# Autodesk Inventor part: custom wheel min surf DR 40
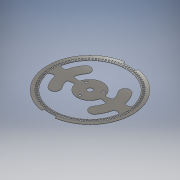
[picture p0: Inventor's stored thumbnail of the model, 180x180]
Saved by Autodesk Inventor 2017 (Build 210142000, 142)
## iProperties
Created: 2016-09
Part Number: custom wheel min surf DR 40
Material: Generic
Document SubType Name: Modeling
Designer: Radek
Density: 1 g/cm^3
Appearance: Mirror
Author: Radek
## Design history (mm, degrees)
workplane "Work Plane1"
sketch "Sketch1"
  geometry: L1 (-46.781, 4.422)-(-44.253, 4.183) reference; L2 (-44.362, 2.791)-(-46.897, 2.951) reference; L3 (-46.411, 7.351)-(-43.903, 6.954) reference; L4 (-44.099, 5.571)-(-46.619, 5.889) reference; L5 (-45.858, 10.251)-(-43.38, 9.696) reference; L6 (-43.663, 8.329)-(-46.158, 8.805) reference; L7 (-45.124, 13.11)-(-42.685, 12.401) reference; L8 (-43.054, 11.054)-(-45.514, 11.686) reference; L9 (-44.212, 15.917)-(-41.822, 15.057) reference; L10 (-42.274, 13.736)-(-44.69, 14.521) reference; L11 (-43.125, 18.662)-(-40.794, 17.653) reference; L12 (-41.329, 16.363)-(-43.69, 17.298) reference; L13 (-41.868, 21.333)-(-39.605, 20.18) reference; L14 (-40.22, 18.926)-(-42.518, 20.007) reference; L15 (-40.446, 23.92)-(-38.26, 22.627) reference; L16 (-38.952, 21.414)-(-41.178, 22.638) reference; L17 (-38.865, 26.412)-(-36.764, 24.985) reference; L18 (-37.53, 23.818)-(-39.675, 25.179) reference; L19 (-37.129, 28.801)-(-35.122, 27.244) reference; L20 (-35.961, 26.127)-(-38.016, 27.62) reference; L21 (-35.248, 31.075)-(-33.342, 29.395) reference; L22 (-34.249, 28.333)-(-36.206, 29.953) reference; L23 (-33.227, 33.227)-(-31.431, 31.431) reference; L24 (-32.403, 30.428)-(-34.254, 32.167) reference; L25 (-31.075, 35.248)-(-29.395, 33.342) reference; L26 (-30.428, 32.403)-(-32.167, 34.254) reference; L27 (-28.801, 37.129)-(-27.244, 35.122) reference; L28 (-28.333, 34.249)-(-29.953, 36.206) reference; L29 (-26.412, 38.865)-(-24.985, 36.764) reference; L30 (-26.127, 35.961)-(-27.62, 38.016) reference; L31 (-23.92, 40.446)-(-22.627, 38.26) reference; L32 (-23.818, 37.53)-(-25.179, 39.675) reference; L33 (-21.333, 41.868)-(-20.18, 39.605) reference; L34 (-21.414, 38.952)-(-22.638, 41.178) reference; L35 (-18.662, 43.125)-(-17.653, 40.794) reference; L36 (-18.926, 40.22)-(-20.007, 42.518) reference; L37 (-15.917, 44.212)-(-15.057, 41.822) reference; L38 (-16.363, 41.329)-(-17.298, 43.69) reference; L39 (-13.11, 45.124)-(-12.401, 42.685) reference; L40 (-13.736, 42.274)-(-14.521, 44.69) reference; L41 (-10.251, 45.858)-(-9.696, 43.38) reference; L42 (-11.054, 43.054)-(-11.686, 45.514) reference; L43 (-7.351, 46.411)-(-6.954, 43.903) reference; L44 (-8.329, 43.663)-(-8.805, 46.158) reference; L45 (-4.422, 46.781)-(-4.183, 44.253) reference; L46 (-5.571, 44.099)-(-5.889, 46.619) reference; L47 (-1.476, 46.967)-(-1.396, 44.428) reference; L48 (-2.791, 44.362)-(-2.951, 46.897) reference; L49 (1.476, 46.967)-(1.396, 44.428) reference; L50 (0, 44.45)-(0, 46.99) reference; L51 (4.422, 46.781)-(4.183, 44.253) reference; L52 (2.791, 44.362)-(2.951, 46.897) reference; L53 (7.351, 46.411)-(6.954, 43.903) reference; L54 (5.571, 44.099)-(5.889, 46.619) reference; L55 (10.251, 45.858)-(9.696, 43.38) reference; L56 (8.329, 43.663)-(8.805, 46.158) reference; L57 (13.11, 45.124)-(12.401, 42.685) reference; L58 (11.054, 43.054)-(11.686, 45.514) reference; L59 (15.917, 44.212)-(15.057, 41.822) reference; L60 (13.736, 42.274)-(14.521, 44.69) reference; L61 (18.662, 43.125)-(17.653, 40.794) reference; L62 (16.363, 41.329)-(17.298, 43.69) reference; L63 (21.333, 41.868)-(20.18, 39.605) reference; L64 (18.926, 40.22)-(20.007, 42.518) reference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; C1 r 50.8 at (0, 0) reference; C2 r 2.984 at (0, 0) reference; C3 r 1.524 at (0, 6.553) reference; C4 r 1.524 at (10.339, 5.969) reference; C5 r 2.984 at (0, 0) reference; C6 r 1.524 at (0, -11.938) reference; C7 r 1.524 at (-5.675, -3.277) reference; C8 r 1.524 at (-10.339, 5.969) reference; C9 r 1.524 at (5.675, -3.277) reference; C10 r 50.8 at (0, 0) reference; C11 r 1.524 at (-5.675, -3.277) reference; C12 r 1.524 at (-10.339, 5.969) reference; C13 r 1.524 at (0, 6.553) reference; C14 r 1.524 at (10.339, 5.969) reference; C15 r 1.524 at (5.675, -3.277) reference; C16 r 1.524 at (0, -11.938) reference; C17 r 2.984 at (0, 0) reference; A1 r 17.081 centre (0, 0) between (0, -17.081) and (17.081, 0) reference; A2 r 17.081 centre (0, 0) between (0, 17.081) and (-17.081, 0) reference; A3 r 43.18 centre (0, 0) between (0, 43.18) and (-43.18, 0) reference; A4 r 43.18 centre (0, 0) between (0, -43.18) and (43.18, 0) reference; A5 r 44.45 centre (0, 0) between (-44.253, 4.183) and (-44.362, 2.791) reference; A6 r 46.99 centre (0, 0) between (-46.781, 4.422) and (-46.897, 2.951) reference; A7 r 44.45 centre (0, 0) between (-43.903, 6.954) and (-44.099, 5.571) reference; A8 r 46.99 centre (0, 0) between (-46.411, 7.351) and (-46.619, 5.889) reference; A9 r 44.45 centre (0, 0) between (-43.38, 9.696) and (-43.663, 8.329) reference; A10 r 46.99 centre (0, 0) between (-45.858, 10.251) and (-46.158, 8.805) reference; A11 r 44.45 centre (0, 0) between (-42.685, 12.401) and (-43.054, 11.054) reference; A12 r 46.99 centre (0, 0) between (-45.124, 13.11) and (-45.514, 11.686) reference; A13 r 44.45 centre (0, 0) between (-41.822, 15.057) and (-42.274, 13.736) reference; A14 r 46.99 centre (0, 0) between (-44.212, 15.917) and (-44.69, 14.521) reference; A15 r 44.45 centre (0, 0) between (-40.794, 17.653) and (-41.329, 16.363) reference; A16 r 46.99 centre (0, 0) between (-43.125, 18.662) and (-43.69, 17.298) reference; A17 r 44.45 centre (0, 0) between (-39.605, 20.18) and (-40.22, 18.926) reference; A18 r 46.99 centre (0, 0) between (-41.868, 21.333) and (-42.518, 20.007) reference; A19 r 44.45 centre (0, 0) between (-38.26, 22.627) and (-38.952, 21.414) reference; A20 r 46.99 centre (0, 0) between (-40.446, 23.92) and (-41.178, 22.638) reference; A21 r 44.45 centre (0, 0) between (-36.764, 24.985) and (-37.53, 23.818) reference; A22 r 46.99 centre (0, 0) between (-38.865, 26.412) and (-39.675, 25.179) reference; A23 r 44.45 centre (0, 0) between (-35.122, 27.244) and (-35.961, 26.127) reference; A24 r 46.99 centre (0, 0) between (-37.129, 28.801) and (-38.016, 27.62) reference; A25 r 44.45 centre (0, 0) between (-33.342, 29.395) and (-34.249, 28.333) reference; A26 r 46.99 centre (0, 0) between (-35.248, 31.075) and (-36.206, 29.953) reference; A27 r 44.45 centre (0, 0) between (-31.431, 31.431) and (-32.403, 30.428) reference; A28 r 46.99 centre (0, 0) between (-33.227, 33.227) and (-34.254, 32.167) reference; A29 r 44.45 centre (0, 0) between (-29.395, 33.342) and (-30.428, 32.403) reference; A30 r 46.99 centre (0, 0) between (-31.075, 35.248) and (-32.167, 34.254) reference; A31 r 44.45 centre (0, 0) between (-27.244, 35.122) and (-28.333, 34.249) reference; A32 r 46.99 centre (0, 0) between (-28.801, 37.129) and (-29.953, 36.206) reference; A33 r 44.45 centre (0, 0) between (-24.985, 36.764) and (-26.127, 35.961) reference; A34 r 46.99 centre (0, 0) between (-26.412, 38.865) and (-27.62, 38.016) reference; A35 r 44.45 centre (0, 0) between (-22.627, 38.26) and (-23.818, 37.53) reference; A36 r 46.99 centre (0, 0) between (-23.92, 40.446) and (-25.179, 39.675) reference; A37 r 44.45 centre (0, 0) between (-20.18, 39.605) and (-21.414, 38.952) reference; A38 r 46.99 centre (0, 0) between (-21.333, 41.868) and (-22.638, 41.178) reference; A39 r 44.45 centre (0, 0) between (-17.653, 40.794) and (-18.926, 40.22) reference; A40 r 46.99 centre (0, 0) between (-18.662, 43.125) and (-20.007, 42.518) reference; A41 r 44.45 centre (0, 0) between (-15.057, 41.822) and (-16.363, 41.329) reference; A42 r 46.99 centre (0, 0) between (-15.917, 44.212) and (-17.298, 43.69) reference; A43 r 44.45 centre (0, 0) between (-12.401, 42.685) and (-13.736, 42.274) reference; A44 r 46.99 centre (0, 0) between (-13.11, 45.124) and (-14.521, 44.69) reference; A45 r 44.45 centre (0, 0) between (-9.696, 43.38) and (-11.054, 43.054) reference; A46 r 46.99 centre (0, 0) between (-10.251, 45.858) and (-11.686, 45.514) reference; A47 r 44.45 centre (0, 0) between (-6.954, 43.903) and (-8.329, 43.663) reference; A48 r 46.99 centre (0, 0) between (-7.351, 46.411) and (-8.805, 46.158) reference; A49 r 44.45 centre (0, 0) between (-4.183, 44.253) and (-5.571, 44.099) reference; A50 r 46.99 centre (0, 0) between (-4.422, 46.781) and (-5.889, 46.619) reference; A51 r 44.45 centre (0, 0) between (-1.396, 44.428) and (-2.791, 44.362) reference; A52 r 46.99 centre (0, 0) between (-1.476, 46.967) and (-2.951, 46.897) reference; A53 r 44.45 centre (0, 0) between (1.396, 44.428) and (0, 44.45) reference; A54 r 46.99 centre (0, 0) between (1.476, 46.967) and (0, 46.99) reference; A55 r 44.45 centre (0, 0) between (4.183, 44.253) and (2.791, 44.362) reference; A56 r 46.99 centre (0, 0) between (4.422, 46.781) and (2.951, 46.897) reference; A57 r 44.45 centre (0, 0) between (6.954, 43.903) and (5.571, 44.099) reference; A58 r 46.99 centre (0, 0) between (7.351, 46.411) and (5.889, 46.619) reference; A59 r 44.45 centre (0, 0) between (9.696, 43.38) and (8.329, 43.663) reference; A60 r 46.99 centre (0, 0) between (10.251, 45.858) and (8.805, 46.158) reference; A61 r 44.45 centre (0, 0) between (12.401, 42.685) and (11.054, 43.054) reference; A62 r 46.99 centre (0, 0) between (13.11, 45.124) and (11.686, 45.514) reference; A63 r 44.45 centre (0, 0) between (15.057, 41.822) and (13.736, 42.274) reference; A64 r 46.99 centre (0, 0) between (15.917, 44.212) and (14.521, 44.69) reference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; 1 further point
  constraints: 8 end point, 2 collinear, 1 parallel
extrude "Extrusion2" new body sketch "Sketch1" distance "d2" = 0.3; taper "d3" = 0 deg
sketch "Sketch2"
  geometry: L1 (-46.781, 4.422)-(-44.253, 4.183) reference; L2 (-44.362, 2.791)-(-46.897, 2.951) reference; L3 (-46.411, 7.351)-(-43.903, 6.954) reference; L4 (-44.099, 5.571)-(-46.619, 5.889) reference; L5 (-45.858, 10.251)-(-43.38, 9.696) reference; L6 (-43.663, 8.329)-(-46.158, 8.805) reference; L7 (-45.124, 13.11)-(-42.685, 12.401) reference; L8 (-43.054, 11.054)-(-45.514, 11.686) reference; L9 (-44.212, 15.917)-(-41.822, 15.057) reference; L10 (-42.274, 13.736)-(-44.69, 14.521) reference; L11 (-43.125, 18.662)-(-40.794, 17.653) reference; L12 (-41.329, 16.363)-(-43.69, 17.298) reference; L13 (-41.868, 21.333)-(-39.605, 20.18) reference; L14 (-40.22, 18.926)-(-42.518, 20.007) reference; L15 (-40.446, 23.92)-(-38.26, 22.627) reference; L16 (-38.952, 21.414)-(-41.178, 22.638) reference; L17 (-38.865, 26.412)-(-36.764, 24.985) reference; L18 (-37.53, 23.818)-(-39.675, 25.179) reference; L19 (-37.129, 28.801)-(-35.122, 27.244) reference; L20 (-35.961, 26.127)-(-38.016, 27.62) reference; L21 (-35.248, 31.075)-(-33.342, 29.395) reference; L22 (-34.249, 28.333)-(-36.206, 29.953) reference; L23 (-33.227, 33.227)-(-31.431, 31.431) reference; L24 (-32.403, 30.428)-(-34.254, 32.167) reference; L25 (-31.075, 35.248)-(-29.395, 33.342) reference; L26 (-30.428, 32.403)-(-32.167, 34.254) reference; L27 (-28.801, 37.129)-(-27.244, 35.122) reference; L28 (-28.333, 34.249)-(-29.953, 36.206) reference; L29 (-26.412, 38.865)-(-24.985, 36.764) reference; L30 (-26.127, 35.961)-(-27.62, 38.016) reference; L31 (-23.92, 40.446)-(-22.627, 38.26) reference; L32 (-23.818, 37.53)-(-25.179, 39.675) reference; L33 (-21.333, 41.868)-(-20.18, 39.605) reference; L34 (-21.414, 38.952)-(-22.638, 41.178) reference; L35 (-18.662, 43.125)-(-17.653, 40.794) reference; L36 (-18.926, 40.22)-(-20.007, 42.518) reference; L37 (-15.917, 44.212)-(-15.057, 41.822) reference; L38 (-16.363, 41.329)-(-17.298, 43.69) reference; L39 (-13.11, 45.124)-(-12.401, 42.685) reference; L40 (-13.736, 42.274)-(-14.521, 44.69) reference; L41 (-10.251, 45.858)-(-9.696, 43.38) reference; L42 (-11.054, 43.054)-(-11.686, 45.514) reference; L43 (-7.351, 46.411)-(-6.954, 43.903) reference; L44 (-8.329, 43.663)-(-8.805, 46.158) reference; L45 (-4.422, 46.781)-(-4.183, 44.253) reference; L46 (-5.571, 44.099)-(-5.889, 46.619) reference; L47 (-1.476, 46.967)-(-1.396, 44.428) reference; L48 (-2.791, 44.362)-(-2.951, 46.897) reference; L49 (1.476, 46.967)-(1.396, 44.428) reference; L50 (0, 44.45)-(0, 46.99) reference; L51 (4.422, 46.781)-(4.183, 44.253) reference; L52 (2.791, 44.362)-(2.951, 46.897) reference; L53 (7.351, 46.411)-(6.954, 43.903) reference; L54 (5.571, 44.099)-(5.889, 46.619) reference; L55 (10.251, 45.858)-(9.696, 43.38) reference; L56 (8.329, 43.663)-(8.805, 46.158) reference; L57 (13.11, 45.124)-(12.401, 42.685) reference; L58 (11.054, 43.054)-(11.686, 45.514) reference; L59 (15.917, 44.212)-(15.057, 41.822) reference; L60 (13.736, 42.274)-(14.521, 44.69) reference; L61 (18.662, 43.125)-(17.653, 40.794) reference; L62 (16.363, 41.329)-(17.298, 43.69) reference; L63 (21.333, 41.868)-(20.18, 39.605) reference; L64 (18.926, 40.22)-(20.007, 42.518) reference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; C1 r 50.8 at (0, 0) reference; C2 r 1.524 at (-5.675, -3.277) reference; C3 r 1.524 at (-10.339, 5.969) reference; C4 r 1.524 at (0, 6.553) reference; C5 r 1.524 at (10.339, 5.969) reference; C6 r 1.524 at (5.675, -3.277) reference; C7 r 1.524 at (0, -11.938) reference; C8 r 2.984 at (0, 0) reference; A1 r 44.45 centre (0, 0) between (-44.253, 4.183) and (-44.362, 2.791) reference; A2 r 46.99 centre (0, 0) between (-46.781, 4.422) and (-46.897, 2.951) reference; A3 r 44.45 centre (0, 0) between (-43.903, 6.954) and (-44.099, 5.571) reference; A4 r 46.99 centre (0, 0) between (-46.411, 7.351) and (-46.619, 5.889) reference; A5 r 44.45 centre (0, 0) between (-43.38, 9.696) and (-43.663, 8.329) reference; A6 r 46.99 centre (0, 0) between (-45.858, 10.251) and (-46.158, 8.805) reference; A7 r 44.45 centre (0, 0) between (-42.685, 12.401) and (-43.054, 11.054) reference; A8 r 46.99 centre (0, 0) between (-45.124, 13.11) and (-45.514, 11.686) reference; A9 r 44.45 centre (0, 0) between (-41.822, 15.057) and (-42.274, 13.736) reference; A10 r 46.99 centre (0, 0) between (-44.212, 15.917) and (-44.69, 14.521) reference; A11 r 44.45 centre (0, 0) between (-40.794, 17.653) and (-41.329, 16.363) reference; A12 r 46.99 centre (0, 0) between (-43.125, 18.662) and (-43.69, 17.298) reference; A13 r 44.45 centre (0, 0) between (-39.605, 20.18) and (-40.22, 18.926) reference; A14 r 46.99 centre (0, 0) between (-41.868, 21.333) and (-42.518, 20.007) reference; A15 r 44.45 centre (0, 0) between (-38.26, 22.627) and (-38.952, 21.414) reference; A16 r 46.99 centre (0, 0) between (-40.446, 23.92) and (-41.178, 22.638) reference; A17 r 44.45 centre (0, 0) between (-36.764, 24.985) and (-37.53, 23.818) reference; A18 r 46.99 centre (0, 0) between (-38.865, 26.412) and (-39.675, 25.179) reference; A19 r 44.45 centre (0, 0) between (-35.122, 27.244) and (-35.961, 26.127) reference; A20 r 46.99 centre (0, 0) between (-37.129, 28.801) and (-38.016, 27.62) reference; A21 r 44.45 centre (0, 0) between (-33.342, 29.395) and (-34.249, 28.333) reference; A22 r 46.99 centre (0, 0) between (-35.248, 31.075) and (-36.206, 29.953) reference; A23 r 44.45 centre (0, 0) between (-31.431, 31.431) and (-32.403, 30.428) reference; A24 r 46.99 centre (0, 0) between (-33.227, 33.227) and (-34.254, 32.167) reference; A25 r 44.45 centre (0, 0) between (-29.395, 33.342) and (-30.428, 32.403) reference; A26 r 46.99 centre (0, 0) between (-31.075, 35.248) and (-32.167, 34.254) reference; A27 r 44.45 centre (0, 0) between (-27.244, 35.122) and (-28.333, 34.249) reference; A28 r 46.99 centre (0, 0) between (-28.801, 37.129) and (-29.953, 36.206) reference; A29 r 44.45 centre (0, 0) between (-24.985, 36.764) and (-26.127, 35.961) reference; A30 r 46.99 centre (0, 0) between (-26.412, 38.865) and (-27.62, 38.016) reference; A31 r 44.45 centre (0, 0) between (-22.627, 38.26) and (-23.818, 37.53) reference; A32 r 46.99 centre (0, 0) between (-23.92, 40.446) and (-25.179, 39.675) reference; A33 r 44.45 centre (0, 0) between (-20.18, 39.605) and (-21.414, 38.952) reference; A34 r 46.99 centre (0, 0) between (-21.333, 41.868) and (-22.638, 41.178) reference; A35 r 44.45 centre (0, 0) between (-17.653, 40.794) and (-18.926, 40.22) reference; A36 r 46.99 centre (0, 0) between (-18.662, 43.125) and (-20.007, 42.518) reference; A37 r 44.45 centre (0, 0) between (-15.057, 41.822) and (-16.363, 41.329) reference; A38 r 46.99 centre (0, 0) between (-15.917, 44.212) and (-17.298, 43.69) reference; A39 r 44.45 centre (0, 0) between (-12.401, 42.685) and (-13.736, 42.274) reference; A40 r 46.99 centre (0, 0) between (-13.11, 45.124) and (-14.521, 44.69) reference; A41 r 44.45 centre (0, 0) between (-9.696, 43.38) and (-11.054, 43.054) reference; A42 r 46.99 centre (0, 0) between (-10.251, 45.858) and (-11.686, 45.514) reference; A43 r 44.45 centre (0, 0) between (-6.954, 43.903) and (-8.329, 43.663) reference; A44 r 46.99 centre (0, 0) between (-7.351, 46.411) and (-8.805, 46.158) reference; A45 r 44.45 centre (0, 0) between (-4.183, 44.253) and (-5.571, 44.099) reference; A46 r 46.99 centre (0, 0) between (-4.422, 46.781) and (-5.889, 46.619) reference; A47 r 44.45 centre (0, 0) between (-1.396, 44.428) and (-2.791, 44.362) reference; A48 r 46.99 centre (0, 0) between (-1.476, 46.967) and (-2.951, 46.897) reference; A49 r 44.45 centre (0, 0) between (1.396, 44.428) and (0, 44.45) reference; A50 r 46.99 centre (0, 0) between (1.476, 46.967) and (0, 46.99) reference; A51 r 44.45 centre (0, 0) between (4.183, 44.253) and (2.791, 44.362) reference; A52 r 46.99 centre (0, 0) between (4.422, 46.781) and (2.951, 46.897) reference; A53 r 44.45 centre (0, 0) between (6.954, 43.903) and (5.571, 44.099) reference; A54 r 46.99 centre (0, 0) between (7.351, 46.411) and (5.889, 46.619) reference; A55 r 44.45 centre (0, 0) between (9.696, 43.38) and (8.329, 43.663) reference; A56 r 46.99 centre (0, 0) between (10.251, 45.858) and (8.805, 46.158) reference; A57 r 44.45 centre (0, 0) between (12.401, 42.685) and (11.054, 43.054) reference; A58 r 46.99 centre (0, 0) between (13.11, 45.124) and (11.686, 45.514) reference; A59 r 44.45 centre (0, 0) between (15.057, 41.822) and (13.736, 42.274) reference; A60 r 46.99 centre (0, 0) between (15.917, 44.212) and (14.521, 44.69) reference; A61 r 44.45 centre (0, 0) between (17.653, 40.794) and (16.363, 41.329) reference; A62 r 46.99 centre (0, 0) between (18.662, 43.125) and (17.298, 43.69) reference; A63 r 44.45 centre (0, 0) between (20.18, 39.605) and (18.926, 40.22) reference; A64 r 46.99 centre (0, 0) between (21.333, 41.868) and (20.007, 42.518) reference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; 1 further point
  constraints: 8 end point, 1 collinear
extrude "Extrusion3" cut sketch "Sketch2" stored distance "d4" = 0.254; taper "d5" = 0 deg
sketch "Sketch3" dims "d20" = 9.26667 (= 0.5 x holediameter), "d21" = 13.10505 (= 1.41421 x d20)
  geometry: L1 (-10.339, 5.969)-(10.339, 5.969); L2 (0, 0)-(50.8, 0); L3 (0, 44.45)-(0, 46.99) reference; L4 (0, 0)-(0, 50.8); L5 (0, 30)-(0, 16.895); L6 (0, 50.165)-(0, 48.26) reference; L7 (-48.26, 0)-(-50.165, 0) reference; L8 (0, 0)-(29.843, 16.148); L9 (0, 50.8)-(0, 50.165); L10 (11.443, 12.43)-(29.194, 31.713); L11 (-11.443, 12.43)-(-29.194, 31.713); C1 r 2.984 at (0, 0) reference; C2 r 15.25 at (0, 0); C3 r 1.524 at (-10.339, 5.969) reference; C4 r 1.524 at (0, -11.938) reference; C5 r 1.524 at (10.339, 5.969) reference; C6 r 1.524 at (-5.675, -3.277) reference; C7 r 1.524 at (5.675, -3.277) reference; A1 r 50.8 centre (0, 0) between (50.8, 0) and (0, 50.8) reference; A2 r 48.26 centre (0, 0) between (0, 48.26) and (-48.26, 0) reference; A3 r 50.165 centre (0, 0) between (0, 50.165) and (-50.165, 0) reference; A4 r 50.165 centre (0, 0) between (-20.154, -45.939) and (22.037, -45.066); A5 r 48.26 centre (0, 0) between (-19.033, -44.348) and (20.956, -43.472); 3 further points; 3 other entities
  constraints: 16 end point, 8 point on circle, 3 centre point, 3 coincident, 2 midpoint, 2 vertical, 1 collinear, 1 horizontal, 1 parallel, 1 point on line, 1 vertical alignment, 19 other
  dimensions: "d9" = 30.5 diameter of C2; "d18" = 0 distance between parallel lines of L4 L5; "d19" = 30 distance of point (0, 0) L5.start (= offaxis); "d24" = 7.44061 dimension on point (0, 0) L5.start point (-20.318, 22.072) (= 0.5 x angle); "d28" = 7.44061 dimension on point (0, 0) point (20.318, 22.072) L5.start (= 0.5 x angle); "d32" = 0.635 distance of L4.end L6.start (derived)
extrude "Extrusion7" cut sketch "Sketch3" stored distance "d40" = 10; taper "d41" = 0 deg
sketch "Sketch4"
  geometry: L1 (-3.221, 42.985)-(-1.263, 16.848) reference; L2 (1.263, 16.848)-(3.221, 42.985) reference; L3 (3.221, 42.985)-(1.263, 16.848) reference; L4 (-1.263, 16.848)-(-3.221, 42.985) reference; L5 (-1.263, 16.848)-(-3.221, 42.985); L6 (1.263, 16.848)-(3.221, 42.985); C1 r 2.984 at (0, 0) reference; C2 r 50.8 at (0, 0) reference; A1 r 16.895 centre (0, 0) between (1.263, 16.848) and (-1.263, 16.848); A2 r 43.105 centre (0, 0) between (3.221, 42.985) and (-3.221, 42.985); 3 further points; 2 other entities
  constraints: 4 end point, 4 point on circle, 2 centre point, 2 coincident, 2 collinear, 2 other
extrude "Extrusion8" cut sketch "Sketch4" stored distance "d42" = 10; taper "d43" = 0 deg
sketch "Sketch5"
  geometry: L1 (0, 0)-(-7.947, 50.175); L2 (0, 0)-(7.947, 50.175); L3 (7.524, 47.508)-(7.837, 49.483); L4 (-7.524, 47.508)-(-7.837, 49.483); L5 (6.954, 43.903)-(7.351, 46.411) reference; L6 (4.422, 46.781)-(4.183, 44.253) reference; L7 (7.351, 46.411)-(6.954, 43.903) reference; C1 r 2.984 at (0, 0) reference; A1 r 50.8 centre (0, 0) between (-7.947, 50.175) and (7.947, 50.175) reference; A2 r 16.895 centre (0, 0) between (1.263, 16.848) and (-1.263, 16.848) reference; A3 r 43.105 centre (0, 0) between (3.221, 42.985) and (-3.221, 42.985) reference; A4 r 48.1 centre (0, 0) between (7.524, 47.508) and (-7.524, 47.508); A5 r 50.1 centre (0, 0) between (7.837, 49.483) and (-7.837, 49.483); 4 further points; 2 other entities
  constraints: 8 end point, 6 point on circle, 3 point on line, 2 centre point, 2 coincident, 2 collinear, 1 midpoint, 8 other
  dimensions: "d44" = 0.7 radial gap between concentric circles of A1 A5; "d45" = 2 radial gap between concentric circles of A5 A4; "d53" = 18 deg angle of L1 L2
extrude "Extrusion9" cut sketch "Sketch5" stored distance "d46" = 10; taper "d47" = 0 deg
pattern_circular "Circular Pattern3" dims angle "d49" = 360 deg
sketch "Sketch6"
  geometry: L1 (16.895, 0)-(16.848, 0) reference; L2 (42.985, 0)-(43.105, 0) reference; L3 (16.848, -0.3)-(16.895, -0.3) reference; L4 (43.105, -0.3)-(42.985, -0.3) reference; L5 (-50.8, 0)-(50.8, 0) reference; L6 (-50.8, -0.3)-(50.8, -0.3) reference; L7 (16.895, 0)-(43.105, 0); L8 (16.895, -0.3)-(43.105, -0.3); L9 (30, -0.3)-(30, 0); L10 (30, -0.15)-(32.935, -3.085); 1 further point
  constraints: 8 end point, 3 midpoint, 1 collinear, 1 parallel
  dimensions: "d51" = 135 deg angle of L10 L9
workaxis "Work Axis1"
workplane "Work Plane3"
  workplane "Work Plane2"
sketch "Sketch7"
  geometry: L1 (0, -11.938)-(-10.339, 5.969); C1 r 1.524 at (0, -11.938) reference; C2 r 1.524 at (-10.339, 5.969) reference; C3 r 2.984 at (0, 0) reference; C4 r 10.414 at (0, 0); 2 further points
  constraints: 2 end point, 1 centre point, 1 coincident, 1 tangent, 1 other
extrude "Extrusion11" cut sketch "Sketch7" stored distance "d57" = 10; taper "d58" = 0 deg
sketch "Sketch8"
  geometry: L1 (7.837, 49.483)-(7.524, 47.508) reference; L2 (-7.524, 47.508)-(-7.837, 49.483) reference; L3 (-46.967, -1.476)-(-44.428, -1.396) reference; L4 (-44.428, -1.396)-(-44.362, -2.791) reference; L5 (-44.362, -2.791)-(-46.897, -2.951) reference; L6 (-46.897, -2.951)-(-46.967, -1.476) reference; L7 (-46.781, -4.422)-(-44.253, -4.183) reference; L8 (-44.253, -4.183)-(-44.099, -5.571) reference; L9 (-44.099, -5.571)-(-46.619, -5.889) reference; L10 (-46.619, -5.889)-(-46.781, -4.422) reference; L11 (-46.411, -7.351)-(-43.903, -6.954) reference; L12 (-43.903, -6.954)-(-43.663, -8.329) reference; L13 (-43.663, -8.329)-(-46.158, -8.805) reference; L14 (-46.158, -8.805)-(-46.411, -7.351) reference; L15 (-45.858, -10.251)-(-43.38, -9.696) reference; L16 (-43.38, -9.696)-(-43.054, -11.054) reference; L17 (-43.054, -11.054)-(-45.514, -11.686) reference; L18 (-45.514, -11.686)-(-45.858, -10.251) reference; L19 (-45.124, -13.11)-(-42.685, -12.401) reference; L20 (-42.685, -12.401)-(-42.274, -13.736) reference; L21 (-42.274, -13.736)-(-44.69, -14.521) reference; L22 (-44.69, -14.521)-(-45.124, -13.11) reference; L23 (-44.212, -15.917)-(-41.822, -15.057) reference; L24 (-41.822, -15.057)-(-41.329, -16.363) reference; L25 (-41.329, -16.363)-(-43.69, -17.298) reference; L26 (-43.69, -17.298)-(-44.212, -15.917) reference; L27 (-43.125, -18.662)-(-40.794, -17.653) reference; L28 (-40.794, -17.653)-(-40.22, -18.926) reference; L29 (-40.22, -18.926)-(-42.518, -20.007) reference; L30 (-42.518, -20.007)-(-43.125, -18.662) reference; L31 (-41.868, -21.333)-(-39.605, -20.18) reference; L32 (-39.605, -20.18)-(-38.952, -21.414) reference; L33 (-38.952, -21.414)-(-41.178, -22.638) reference; L34 (-41.178, -22.638)-(-41.868, -21.333) reference; L35 (-40.446, -23.92)-(-38.26, -22.627) reference; L36 (-38.26, -22.627)-(-37.53, -23.818) reference; L37 (-37.53, -23.818)-(-39.675, -25.179) reference; L38 (-39.675, -25.179)-(-40.446, -23.92) reference; L39 (-38.865, -26.412)-(-36.764, -24.985) reference; L40 (-36.764, -24.985)-(-35.961, -26.127) reference; L41 (-35.961, -26.127)-(-38.016, -27.62) reference; L42 (-38.016, -27.62)-(-38.865, -26.412) reference; L43 (-37.129, -28.801)-(-35.122, -27.244) reference; L44 (-35.122, -27.244)-(-34.249, -28.333) reference; L45 (-34.249, -28.333)-(-36.206, -29.953) reference; L46 (-36.206, -29.953)-(-37.129, -28.801) reference; L47 (-35.248, -31.075)-(-33.342, -29.395) reference; L48 (-33.342, -29.395)-(-32.403, -30.428) reference; L49 (-32.403, -30.428)-(-34.254, -32.167) reference; L50 (-34.254, -32.167)-(-35.248, -31.075) reference; L51 (-33.227, -33.227)-(-31.431, -31.431) reference; L52 (-31.431, -31.431)-(-30.428, -32.403) reference; L53 (-30.428, -32.403)-(-32.167, -34.254) reference; L54 (-32.167, -34.254)-(-33.227, -33.227) reference; L55 (-31.075, -35.248)-(-29.395, -33.342) reference; L56 (-29.395, -33.342)-(-28.333, -34.249) reference; L57 (-28.333, -34.249)-(-29.953, -36.206) reference; L58 (-29.953, -36.206)-(-31.075, -35.248) reference; L59 (-28.801, -37.129)-(-27.244, -35.122) reference; L60 (-27.244, -35.122)-(-26.127, -35.961) reference; L61 (-26.127, -35.961)-(-27.62, -38.016) reference; L62 (-27.62, -38.016)-(-28.801, -37.129) reference; L63 (-26.412, -38.865)-(-24.985, -36.764) reference; L64 (-24.985, -36.764)-(-23.818, -37.53) reference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; C1 r 2.984 at (0, 0) reference; C2 r 1.524 at (5.675, -3.277) reference; C3 r 1.524 at (-10.339, 5.969) reference; C4 r 1.524 at (-5.675, -3.277) reference; C5 r 1.524 at (0, -11.938) reference; C6 r 1.524 at (10.339, 5.969) reference; C7 r 1.524 at (0, 6.553) reference; C8 r 50.8 at (0, 0) reference; C9 r 2.984 at (0, 0) reference; A1 r 48.1 centre (0, 0) between (7.524, 47.508) and (-7.524, 47.508) reference; A2 r 50.1 centre (0, 0) between (7.837, 49.483) and (-7.837, 49.483) reference; A3 r 43.105 centre (0, 0) between (3.221, 42.985) and (-3.221, 42.985) reference; A4 r 16.895 centre (0, 0) between (1.263, 16.848) and (-1.263, 16.848) reference; A5 r 43.105 centre (0, 0) between (-3.221, -42.985) and (3.221, -42.985); A6 r 16.895 centre (0, 0) between (-1.263, -16.848) and (1.263, -16.848); 3 further points; 1 other entity
  constraints: 8 end point, 4 point on circle, 2 centre point, 2 coincident, 2 collinear, 2 point on line, 2 other
extrude "Extrusion12" cut sketch "Sketch8" stored distance "d59" = 10; taper "d60" = 0 deg
pattern_circular "Circular Pattern4" dims angle "d62" = 360 deg
sketch "Sketch9"
  geometry: L1 (-44.45, 0)-(-46.99, 0) reference; L2 (-46.99, 0)-(-46.967, 1.476) reference; L3 (-46.967, 1.476)-(-44.428, 1.396) reference; L4 (-44.428, 1.396)-(-44.45, 0) reference; L5 (-46.781, 4.422)-(-44.253, 4.183) reference; L6 (-44.253, 4.183)-(-44.362, 2.791) reference; L7 (-44.362, 2.791)-(-46.897, 2.951) reference; L8 (-46.897, 2.951)-(-46.781, 4.422) reference; L9 (-46.411, 7.351)-(-43.903, 6.954) reference; L10 (-43.903, 6.954)-(-44.099, 5.571) reference; L11 (-44.099, 5.571)-(-46.619, 5.889) reference; L12 (-46.619, 5.889)-(-46.411, 7.351) reference; L13 (-45.858, 10.251)-(-43.38, 9.696) reference; L14 (-43.38, 9.696)-(-43.663, 8.329) reference; L15 (-43.663, 8.329)-(-46.158, 8.805) reference; L16 (-46.158, 8.805)-(-45.858, 10.251) reference; L17 (-45.124, 13.11)-(-42.685, 12.401) reference; L18 (-42.685, 12.401)-(-43.054, 11.054) reference; L19 (-43.054, 11.054)-(-45.514, 11.686) reference; L20 (-45.514, 11.686)-(-45.124, 13.11) reference; L21 (-44.212, 15.917)-(-41.822, 15.057) reference; L22 (-41.822, 15.057)-(-42.274, 13.736) reference; L23 (-42.274, 13.736)-(-44.69, 14.521) reference; L24 (-44.69, 14.521)-(-44.212, 15.917) reference; L25 (-43.125, 18.662)-(-40.794, 17.653) reference; L26 (-40.794, 17.653)-(-41.329, 16.363) reference; L27 (-41.329, 16.363)-(-43.69, 17.298) reference; L28 (-43.69, 17.298)-(-43.125, 18.662) reference; L29 (-41.868, 21.333)-(-39.605, 20.18) reference; L30 (-39.605, 20.18)-(-40.22, 18.926) reference; L31 (-40.22, 18.926)-(-42.518, 20.007) reference; L32 (-42.518, 20.007)-(-41.868, 21.333) reference; L33 (-40.446, 23.92)-(-38.26, 22.627) reference; L34 (-38.26, 22.627)-(-38.952, 21.414) reference; L35 (-38.952, 21.414)-(-41.178, 22.638) reference; L36 (-41.178, 22.638)-(-40.446, 23.92) reference; L37 (-38.865, 26.412)-(-36.764, 24.985) reference; L38 (-36.764, 24.985)-(-37.53, 23.818) reference; L39 (-37.53, 23.818)-(-39.675, 25.179) reference; L40 (-39.675, 25.179)-(-38.865, 26.412) reference; L41 (-37.129, 28.801)-(-35.122, 27.244) reference; L42 (-35.122, 27.244)-(-35.961, 26.127) reference; L43 (-35.961, 26.127)-(-38.016, 27.62) reference; L44 (-38.016, 27.62)-(-37.129, 28.801) reference; L45 (-35.248, 31.075)-(-33.342, 29.395) reference; L46 (-33.342, 29.395)-(-34.249, 28.333) reference; L47 (-34.249, 28.333)-(-36.206, 29.953) reference; L48 (-36.206, 29.953)-(-35.248, 31.075) reference; L49 (-33.227, 33.227)-(-31.431, 31.431) reference; L50 (-31.431, 31.431)-(-32.403, 30.428) reference; L51 (-32.403, 30.428)-(-34.254, 32.167) reference; L52 (-34.254, 32.167)-(-33.227, 33.227) reference; L53 (-31.075, 35.248)-(-29.395, 33.342) reference; L54 (-29.395, 33.342)-(-30.428, 32.403) reference; L55 (-30.428, 32.403)-(-32.167, 34.254) reference; L56 (-32.167, 34.254)-(-31.075, 35.248) reference; L57 (-28.801, 37.129)-(-27.244, 35.122) reference; L58 (-27.244, 35.122)-(-28.333, 34.249) reference; L59 (-28.333, 34.249)-(-29.953, 36.206) reference; L60 (-29.953, 36.206)-(-28.801, 37.129) reference; L61 (-26.412, 38.865)-(-24.985, 36.764) reference; L62 (-24.985, 36.764)-(-26.127, 35.961) reference; L63 (-26.127, 35.961)-(-27.62, 38.016) reference; L64 (-27.62, 38.016)-(-26.412, 38.865) reference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; C1 r 50.8 at (0, 0) reference; C2 r 1.524 at (0, 6.553) reference; C3 r 1.524 at (10.339, 5.969) reference; C4 r 1.524 at (0, -11.938) reference; C5 r 1.524 at (-5.675, -3.277) reference; C6 r 1.524 at (-10.339, 5.969) reference; C7 r 1.524 at (5.675, -3.277) reference; C8 r 2.984 at (0, 0) reference; C9 r 2.984 at (0, 0) reference; A1 r 16.895 centre (0, 0) between (1.263, 16.848) and (-1.263, 16.848) reference; A2 r 48.1 centre (0, 0) between (7.524, 47.508) and (-7.524, 47.508) reference; A3 r 50.1 centre (0, 0) between (7.837, 49.483) and (-7.837, 49.483) reference; A4 r 48.1 centre (0, 0) between (-7.524, -47.508) and (7.524, -47.508); A5 r 55.8 centre (0, 0) between (-8.729, -55.113) and (8.729, -55.113); A6 r 43.105 centre (0, 0) between (3.221, 42.985) and (-3.221, 42.985) reference; 2 further points
  constraints: 8 end point, 4 point on circle, 4 point on line, 2 centre point, 2 coincident, 2 collinear
  dimensions: "d64" = 5 radial gap between concentric circles of C1 A5
extrude "Extrusion13" cut sketch "Sketch9" stored distance "d65" = 10; taper "d66" = 0 deg
pattern_circular "Circular Pattern5" dims angle "d68" = 360 deg
fillet "Fillet1" dims "d70" = 0.5 (derived)
fillet "Fillet3" dims "d72" = 0.5 (derived)
pattern_circular "Circular Pattern7" dims angle "d77" = 360 deg
sketch "Sketch10"
  geometry: C1 r 1.524 at (-5.675, -3.277) reference; C2 r 1.524 at (0, 6.553) reference; C3 r 1.524 at (5.675, -3.277) reference; 1 further point
extrude "Extrusion14" join sketch "Sketch10" stored distance "d79" = 10; taper "d80" = 0 deg
sketch "Sketch11"
  geometry: L1 (7.868, 49.678)-(7.602, 47.999) reference; L2 (-7.602, 47.999)-(-7.868, 49.678) reference; L3 (-7.868, -49.678)-(-7.602, -47.999) reference; L4 (7.602, -47.999)-(7.868, -49.678) reference; L5 (-44.942, 0)-(-46.482, 0) reference; L6 (-46.982, 0.508)-(-46.975, 0.968) reference; L7 (-46.459, 1.46)-(-44.92, 1.412) reference; L8 (-44.436, 0.904)-(-44.442, 0.492) reference; L9 (-46.276, 4.374)-(-44.743, 4.229) reference; L10 (-44.291, 3.692)-(-44.324, 3.282) reference; L11 (-44.854, 2.822)-(-46.39, 2.919) reference; L12 (-46.857, 3.457)-(-46.821, 3.916) reference; L13 (-45.91, 7.271)-(-44.389, 7.031) reference; L14 (-43.972, 6.466)-(-44.03, 6.058) reference; L15 (-44.588, 5.633)-(-46.116, 5.826) reference; L16 (-46.548, 6.392)-(-46.483, 6.848) reference; L17 (-45.363, 10.14)-(-43.86, 9.804) reference; L18 (-43.479, 9.214)-(-43.563, 8.811) reference; L19 (-44.146, 8.421)-(-45.659, 8.71) reference; L20 (-46.055, 9.302)-(-45.961, 9.753) reference; L21 (-44.636, 12.968)-(-43.158, 12.538) reference; L22 (-42.815, 11.926)-(-42.924, 11.529) reference; L23 (-43.53, 11.177)-(-45.022, 11.56) reference; L24 (-45.38, 12.176)-(-45.258, 12.62) reference; L25 (-43.734, 15.745)-(-42.285, 15.224) reference; L26 (-41.982, 14.591)-(-42.115, 14.201) reference; L27 (-42.743, 13.888)-(-44.207, 14.364) reference; L28 (-44.526, 15.001)-(-44.377, 15.437) reference; L29 (-42.659, 18.46)-(-41.246, 17.849) reference; L30 (-40.983, 17.198)-(-41.14, 16.818) reference; L31 (-41.786, 16.544)-(-43.218, 17.111) reference; L32 (-43.496, 17.767)-(-43.32, 18.193) reference; L33 (-41.416, 21.102)-(-40.044, 20.403) reference; L34 (-39.822, 19.738)-(-40.003, 19.368) reference; L35 (-40.665, 19.135)-(-42.058, 19.791) reference; L36 (-42.294, 20.463)-(-42.092, 20.877) reference; L37 (-40.009, 23.661)-(-38.684, 22.877) reference; L38 (-38.504, 22.199)-(-38.708, 21.841) reference; L39 (-39.383, 21.651)-(-40.733, 22.393) reference; L40 (-40.926, 23.079)-(-40.698, 23.479) reference; L41 (-38.444, 26.127)-(-37.171, 25.261) reference; L42 (-37.034, 24.573)-(-37.26, 24.229) reference; L43 (-37.946, 24.081)-(-39.246, 24.906) reference; L44 (-39.396, 25.603)-(-39.143, 25.988) reference; L45 (-36.728, 28.489)-(-35.511, 27.545) reference; L46 (-35.418, 26.85)-(-35.665, 26.521) reference; L47 (-36.359, 26.416)-(-37.605, 27.321) reference; L48 (-37.711, 28.026)-(-37.434, 28.394) reference; L49 (-34.867, 30.739)-(-33.712, 29.721) reference; L50 (-33.662, 29.021)-(-33.93, 28.708) reference; L51 (-34.629, 28.647)-(-35.815, 29.629) reference; L52 (-35.877, 30.339)-(-35.578, 30.689) reference; L53 (-32.868, 32.868)-(-31.779, 31.779) reference; L54 (-31.773, 31.077)-(-32.06, 30.782) reference; L55 (-32.761, 30.765)-(-33.884, 31.819) reference; L56 (-33.901, 32.532)-(-33.58, 32.862) reference; L57 (-30.739, 34.867)-(-29.721, 33.712) reference; L58 (-29.759, 33.011)-(-30.064, 32.734) reference; L59 (-30.765, 32.761)-(-31.819, 33.884) reference; L60 (-31.791, 34.596)-(-31.451, 34.906) reference; L61 (-28.489, 36.728)-(-27.545, 35.511) reference; L62 (-27.628, 34.815)-(-27.949, 34.557) reference; L63 (-28.647, 34.629)-(-29.629, 35.815) reference; L64 (-29.556, 36.524)-(-29.197, 36.812) reference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; C1 r 1.524 at (10.339, 5.969) reference; C2 r 1.524 at (0, -11.938) reference; C3 r 1.524 at (-10.339, 5.969) reference; C4 r 2.984 at (0, 0) reference; C5 r 2.984 at (0, 0) reference; A1 r 0.5 centre (8.362, 49.6) between (8.445, 50.093) and (7.868, 49.678) reference; A2 r 48.1 centre (0, 0) between (7.035, 47.583) and (-7.035, 47.583) reference; A3 r 0.5 centre (-8.362, 49.6) between (-7.868, 49.678) and (-8.445, 50.093) reference; A4 r 50.8 centre (0, 0) between (-8.445, 50.093) and (-8.445, -50.093) reference; A5 r 0.5 centre (-8.362, -49.6) between (-8.445, -50.093) and (-7.868, -49.678) reference; A6 r 0.5 centre (-7.108, -48.077) between (-7.035, -47.583) and (-7.602, -47.999) reference; A7 r 48.1 centre (0, 0) between (-7.035, -47.583) and (7.035, -47.583) reference; A8 r 0.5 centre (7.108, -48.077) between (7.602, -47.999) and (7.035, -47.583) reference; A9 r 0.5 centre (8.362, -49.6) between (7.868, -49.678) and (8.445, -50.093) reference; A10 r 50.8 centre (0, 0) between (8.445, -50.093) and (8.445, 50.093) reference; A11 r 0.5 centre (-46.482, 0.5) between (-46.982, 0.508) and (-46.482, 0) reference; A12 r 0.5 centre (-46.475, 0.96) between (-46.459, 1.46) and (-46.975, 0.968) reference; A13 r 0.5 centre (-44.936, 0.912) between (-44.436, 0.904) and (-44.92, 1.412) reference; A14 r 0.5 centre (-44.942, 0.5) between (-44.942, 0) and (-44.442, 0.492) reference; A15 r 0.5 centre (-44.79, 3.732) between (-44.291, 3.692) and (-44.743, 4.229) reference; A16 r 0.5 centre (-44.822, 3.321) between (-44.854, 2.822) and (-44.324, 3.282) reference; A17 r 0.5 centre (-46.359, 3.418) between (-46.857, 3.457) and (-46.39, 2.919) reference; A18 r 0.5 centre (-46.323, 3.877) between (-46.276, 4.374) and (-46.821, 3.916) reference; A19 r 0.5 centre (-44.467, 6.537) between (-43.972, 6.466) and (-44.389, 7.031) reference; A20 r 0.5 centre (-44.525, 6.129) between (-44.588, 5.633) and (-44.03, 6.058) reference; A21 r 0.5 centre (-46.053, 6.322) between (-46.548, 6.392) and (-46.116, 5.826) reference; A22 r 0.5 centre (-45.988, 6.778) between (-45.91, 7.271) and (-46.483, 6.848) reference; A23 r 0.5 centre (-43.969, 9.316) between (-43.479, 9.214) and (-43.86, 9.804) reference; A24 r 0.5 centre (-44.052, 8.912) between (-44.146, 8.421) and (-43.563, 8.811) reference; A25 r 0.5 centre (-45.565, 9.201) between (-46.055, 9.302) and (-45.659, 8.71) reference; A26 r 0.5 centre (-45.472, 9.652) between (-45.363, 10.14) and (-45.961, 9.753) reference; A27 r 0.5 centre (-43.297, 12.058) between (-42.815, 11.926) and (-43.158, 12.538) reference; A28 r 0.5 centre (-43.406, 11.661) between (-43.53, 11.177) and (-42.924, 11.529) reference; A29 r 0.5 centre (-44.897, 12.044) between (-45.38, 12.176) and (-45.022, 11.56) reference; A30 r 0.5 centre (-44.776, 12.488) between (-44.636, 12.968) and (-45.258, 12.62) reference; A31 r 0.5 centre (-42.455, 14.753) between (-41.982, 14.591) and (-42.285, 15.224) reference; A32 r 0.5 centre (-42.588, 14.363) between (-42.743, 13.888) and (-42.115, 14.201) reference; A33 r 0.5 centre (-44.053, 14.839) between (-44.526, 15.001) and (-44.207, 14.364) reference; A34 r 0.5 centre (-43.903, 15.275) between (-43.734, 15.745) and (-44.377, 15.437) reference; A35 r 0.5 centre (-41.444, 17.39) between (-40.983, 17.198) and (-41.246, 17.849) reference; A36 r 0.5 centre (-41.602, 17.009) between (-41.786, 16.544) and (-41.14, 16.818) reference; A37 r 0.5 centre (-43.034, 17.576) between (-43.496, 17.767) and (-43.218, 17.111) reference; A38 r 0.5 centre (-42.858, 18.001) between (-42.659, 18.46) and (-43.32, 18.193) reference; A39 r 0.5 centre (-40.271, 19.958) between (-39.822, 19.738) and (-40.044, 20.403) reference; A40 r 0.5 centre (-40.452, 19.588) between (-40.665, 19.135) and (-40.003, 19.368) reference; A41 r 0.5 centre (-41.845, 20.244) between (-42.294, 20.463) and (-42.058, 19.791) reference; A42 r 0.5 centre (-41.643, 20.657) between (-41.416, 21.102) and (-42.092, 20.877) reference; A43 r 0.5 centre (-38.938, 22.447) between (-38.504, 22.199) and (-38.684, 22.877) reference; A44 r 0.5 centre (-39.142, 22.089) between (-39.383, 21.651) and (-38.708, 21.841) reference; A45 r 0.5 centre (-40.492, 22.831) between (-40.926, 23.079) and (-40.733, 22.393) reference; A46 r 0.5 centre (-40.264, 23.231) between (-40.009, 23.661) and (-40.698, 23.479) reference; A47 r 0.5 centre (-37.452, 24.848) between (-37.034, 24.573) and (-37.171, 25.261) reference; A48 r 0.5 centre (-37.678, 24.503) between (-37.946, 24.081) and (-37.26, 24.229) reference; A49 r 0.5 centre (-38.978, 25.329) between (-39.396, 25.603) and (-39.246, 24.906) reference; A50 r 0.5 centre (-38.725, 25.713) between (-38.444, 26.127) and (-39.143, 25.988) reference; A51 r 0.5 centre (-35.818, 27.15) between (-35.418, 26.85) and (-35.511, 27.545) reference; A52 r 0.5 centre (-36.065, 26.821) between (-36.359, 26.416) and (-35.665, 26.521) reference; A53 r 0.5 centre (-37.311, 27.726) between (-37.711, 28.026) and (-37.605, 27.321) reference; A54 r 0.5 centre (-37.035, 28.094) between (-36.728, 28.489) and (-37.434, 28.394) reference; A55 r 0.5 centre (-34.042, 29.346) between (-33.662, 29.021) and (-33.712, 29.721) reference; A56 r 0.5 centre (-34.31, 29.032) between (-34.629, 28.647) and (-33.93, 28.708) reference; A57 r 0.5 centre (-35.496, 30.014) between (-35.877, 30.339) and (-35.815, 29.629) reference; A58 r 0.5 centre (-35.197, 30.364) between (-34.867, 30.739) and (-35.578, 30.689) reference; A59 r 0.5 centre (-32.132, 31.425) between (-31.773, 31.077) and (-31.779, 31.779) reference; A60 r 0.5 centre (-32.419, 31.13) between (-32.761, 30.765) and (-32.06, 30.782) reference; A61 r 0.5 centre (-33.542, 32.184) between (-33.901, 32.532) and (-33.884, 31.819) reference; A62 r 0.5 centre (-33.221, 32.514) between (-32.868, 32.868) and (-33.58, 32.862) reference; A63 r 0.5 centre (-30.096, 33.381) between (-29.759, 33.011) and (-29.721, 33.712) reference; A64 r 0.5 centre (-30.401, 33.104) between (-30.765, 32.761) and (-30.064, 32.734) reference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; 1 further point
  constraints: 11 point on circle, 10 end point, 4 centre point, 4 coincident, 4 point on line, 2 collinear, 1 vertical, 1 other
  dimensions: "d81" = 2 dimension on C1 A413; "d82" = 1 distance edge to line of A414 L114; "d85" = 162 deg angle of L406 L407 (derived)
extrude "Extrusion15" cut sketch "Sketch11" stored distance "d83" = 0; taper "d84" = 0 deg
fillet "Fillet4" dims "d86" = 2
sketch "Sketch12"
  geometry: L1 (-23.801, -18.263)-(0, 0); L2 (0, 0)-(-23.801, 18.263); L3 (0, 0)-(-37.086, 0); C1 r 2.984 at (0, 0) reference; A1 r 30 centre (0, 0) between (-23.801, 18.263) and (-23.801, -18.263); A2 r 36 centre (0, 0) between (-28.561, 21.915) and (-28.561, -21.915); A3 r 24 centre (0, 0) between (-19.04, 14.61) and (-19.04, -14.61); A4 r 6 centre (-23.801, 18.263) between (-19.04, 14.61) and (-28.561, 21.915); A5 r 6 centre (-23.801, -18.263) between (-28.561, -21.915) and (-19.04, -14.61); 1 further point
  constraints: 11 point on circle, 6 end point, 5 centre point, 4 tangent, 1 coincident, 1 horizontal, 1 point on line, 1 other
  dimensions: "d87" = 6 radius of A5; "d88" = 30 radius of A1; "d89" = 75 deg angle of L2 L1
extrude "Extrusion16" join sketch "Sketch12" stored distance "d90" = 10; taper "d91" = 0 deg
fillet "Fillet5" dims "d92" = 2
mirror "Mirror2"
fillet "Fillet6" dims "d93" = 2
body "Solid2"
pattern_circular "Circular Pattern1" dims angle "d7" = 360 deg
pattern_circular "Circular Pattern6" dims angle "d74" = 360 deg
node "Reference1"
node "Reference2"
node "Reference3"
node "Reference4"
node "Reference5"
node "Reference6"
node "Reference7"
node "Reference8"
node "Reference9"
node "Reference10"
node "Reference11"
node "Reference12"
node "Reference13"
node "Reference14"
node "Reference15"
node "Reference16"
node "Reference17"
node "Reference18"
node "Reference19"
node "Projected Loop1"
node "Projected Loop2"
node "Projected Loop3"
other parameters: "d12" = 9.66667 (computed from ftube, FOV), "FOV" = 1.5 [user parameter; used in 2 equation terms], "dutycycle" = 6.70329 (computed from holelength, offaxis) [user parameter], "offaxis" = 30 [user parameter; used in 4 equation terms], "angle" = 14.88123 (computed from holediameter, holelength, offaxis) [user parameter; used in 2 equation terms], "holelength" = 63.17702 (computed from dutyratio, offaxis, holediameter) [user parameter; used in 2 equation terms], "holediameter" = 18.53333 (computed from FOV, ftube) [user parameter; used in 3 equation terms], "dutyratio" = 9 [user parameter; used in 1 equation term], "d52" = 45 deg, "minradius" = 0.5 [user parameter]
